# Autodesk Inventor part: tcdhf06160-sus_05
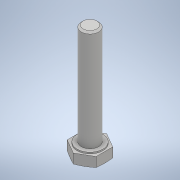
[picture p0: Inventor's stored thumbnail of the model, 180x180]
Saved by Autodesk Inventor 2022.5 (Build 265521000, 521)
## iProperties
Part Number: tcdhf06160-sus_05
Material: 一般
Document SubType Name: Modeling
Designer: ImaoCorp
Density: 1 g/cm^3
Appearance: 既定
Author: ImaoCorp
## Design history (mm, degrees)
feature "tcdhf06160-sus_05"
node "ソリッド1"
